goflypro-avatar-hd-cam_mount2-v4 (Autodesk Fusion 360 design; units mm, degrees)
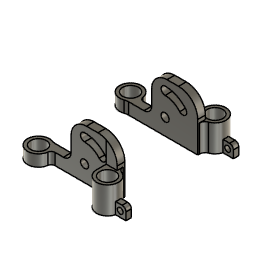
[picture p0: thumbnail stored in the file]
sketch "Skizze1" plane through (0, 0, 0) normal (0, 0, 1) x axis (1, 0, 0)
  line L1 (10, 2.5) -> (-8.6316, 2.5)
  line L2 (10, 0.85) -> (10, 2.5)
  line L3 (7.15, 0.5) -> (-7.1942, 0.5)
  line L4 (-2, 0.5) -> (-2, 2.5)
  line L5 (7.15, 0.5) -> (7.15, -2)
  line L6 (10, 0.5) -> (7.15, 0.5)
  line L7 (10, 0.85) -> (10, 0.5)
  circle C1 centre (-10, 0) radius 2.05
  circle C2 centre (10, -2) radius 2.05
  circle C3 centre (-10, 0) radius 2.85
  circle C4 centre (10, -2) radius 2.85
  point P5 (-2, 2.5)
  point P6 (-2, 0.5)
  point P8 (-8.6316, 2.5)
  point P9 (-7.1942, 0.5)
  point P11 (7.15, -2)
  point P13 (10, 0.85)
  perpendicular L1 L2
  coincident L1 P5
  coincident L3 P6
  concentric C1 C3
  coincident C3 P8
  coincident C3 P9
  coincident C4 P11
  tangent C4 L5
  perpendicular L3 L5
  coincident C4 P13
  perpendicular L5 L6
  perpendicular L6 L7
  dimension "d1" diameter C1 = 4.1
  dimension "d2" diameter C2 = 4.1
  dimension "d87" diameter C3 = 5.7
  dimension "d88" diameter C4 = 5.7
extrude "Extrusion1" new body sketch "Skizze1" profile of L1 L2 L3 L4 C4 L6 L7 along normal blind 13
extrude "Extrusion5" new body sketch "Skizze1" profile of C1 L1 L3 L4 C3 along normal blind 3 bodies "GoFlyPro - Avatar-HD-Cam mount2 - left"
combine "Kombinieren"
sketch "Skizze2" plane through (0, 0.5, 0) normal (0, 1, 0) x axis (1, 0, 0)
  line L1 (7.2, 0) -> (1, 0)
  line L2 (7.2, -7) -> (7.2, 0)
  line L3 (1, -7) -> (7.2, -7)
  line L4 (1, 0) -> (1, -7)
  line L5 (7.15, 0) -> (-7.1942, 0)
  line L6 (-7.1942, -3) -> (-2, -3)
  line L7 (-2, -13) -> (7.15, -13)
  line L8 (-2, -3) -> (-2, -13)
  line L9 (-7.1942, 0) -> (-7.1942, -3)
  line L10 (7.15, -13) -> (7.15, 0)
  circle C1 centre (1.5, -4.25) radius 1.05
  circle C2 centre (6.0963, -8.1067) radius 1.05
  circle C3 centre (1.5, -4.25) radius 4.95
  circle C4 centre (1.5, -4.25) radius 7.05
  circle C5 centre (1.5, -10.25) radius 1.05
  concentric C1 C3
  tangent C2 C3
  concentric C3 C4
  tangent C2 C4
  dimension "d8" diameter C1 = 2.1
  dimension "d31" diameter C2 = 2.1
  dimension "d32" diameter C5 = 2.1
extrude "Extrusion2" cut sketch "Skizze2" profile of C1 C2 C3 C4 C5 L4 along normal blind 2
fillet "Abrundung13" radius 1
fillet "Abrundung17" radius 4
fillet "Abrundung18" radius 2
fillet "Abrundung19" radius 3
sketch "Skizze3" plane through (0, 0, 0) normal (0, 0, 1) x axis (1, 0, 0)
  line L1 (12.5, -2.7) -> (15.5, -2.7)
  line L2 (12.5, -1.3) -> (12.5, -2.7)
  line L3 (15.5, -1.3) -> (12.5, -1.3)
  line L4 (15.5, -2.7) -> (15.5, -1.3)
  horizontal L1
  vertical L2
  horizontal L3
  vertical L4
extrude "Extrusion8" add sketch "Skizze3" along normal blind 3
extrude "Extrusion10" add sketch "Skizze1" profile of C2 C4 L5 L6 L7 along normal blind 7
sketch "Skizze4" plane through (0, -2.7, 0) normal (0, -1, 0) x axis (1, 0, 0)
  line L1 (15.5, 0) -> (12.7627, 0)
  line L2 (15.5, 3) -> (15.5, 0)
  line L3 (12.7627, 3) -> (15.5, 3)
  line L4 (12.7627, 0) -> (12.7627, 3)
  circle C1 centre (14, 1.5) radius 0.75
  dimension "d82" diameter C1 = 1.5
extrude "Extrusion9" cut sketch "Skizze4" profile of C1 against normal blind 2
fillet "Abrundung20" radius 1
fillet "Abrundung21" radius 1.5
fillet "Abrundung22" radius 5
work_plane "Arbeitsebene" AlongDistance 12
mirror "Spiegeln" mirrorStitchTolerance 0.1 bodies "GoFlyPro - Avatar-HD-Cam mount2 - right"
named bodies: "GoFlyPro - Avatar-HD-Cam mount2 - left", "GoFlyPro - Avatar-HD-Cam mount2 - right"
